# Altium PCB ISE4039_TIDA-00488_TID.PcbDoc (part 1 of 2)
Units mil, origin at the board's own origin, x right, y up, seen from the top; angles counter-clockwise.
Board outline 3000 x 2000 mil, 4 copper layers (Layer 1 - Top Layer, Layer 2 - GND, Layer 3 - PWR, Layer 4 - Bottom Layer), stack 32.634 mil thick; 131 components, 56 nets, 369 pads, 363 vias.
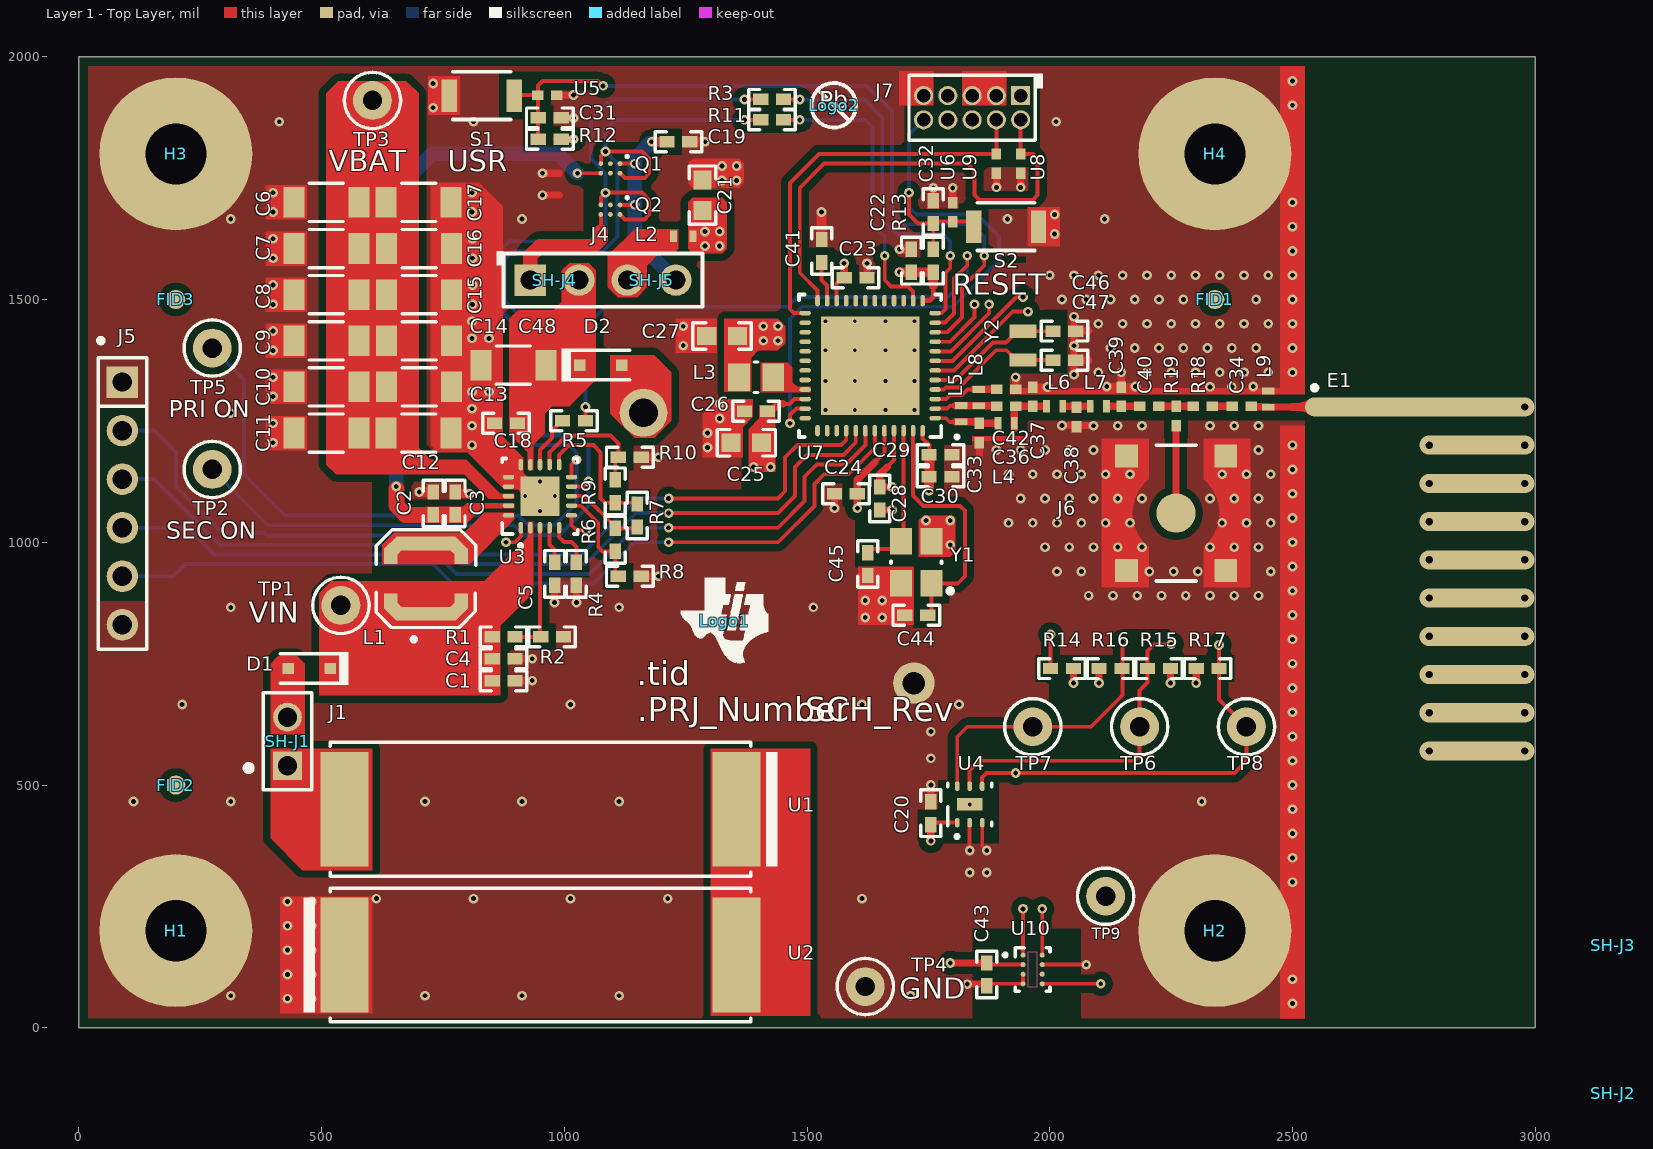
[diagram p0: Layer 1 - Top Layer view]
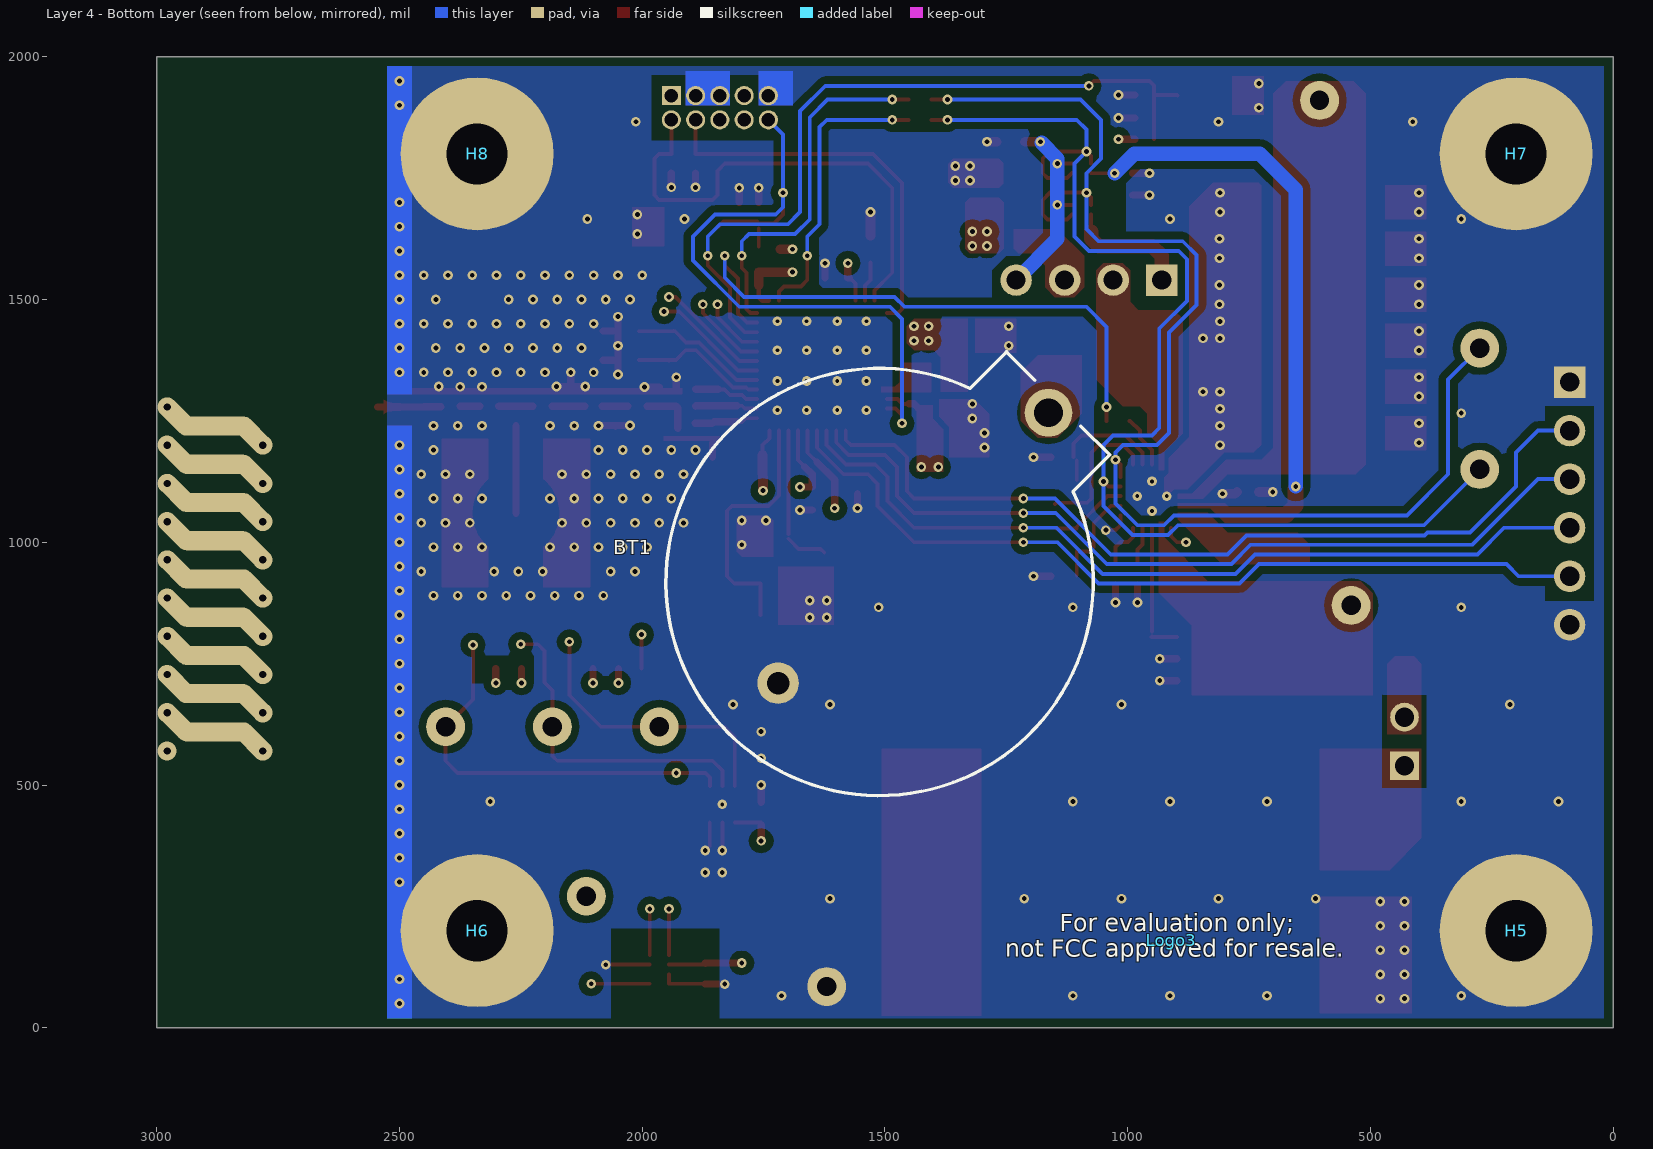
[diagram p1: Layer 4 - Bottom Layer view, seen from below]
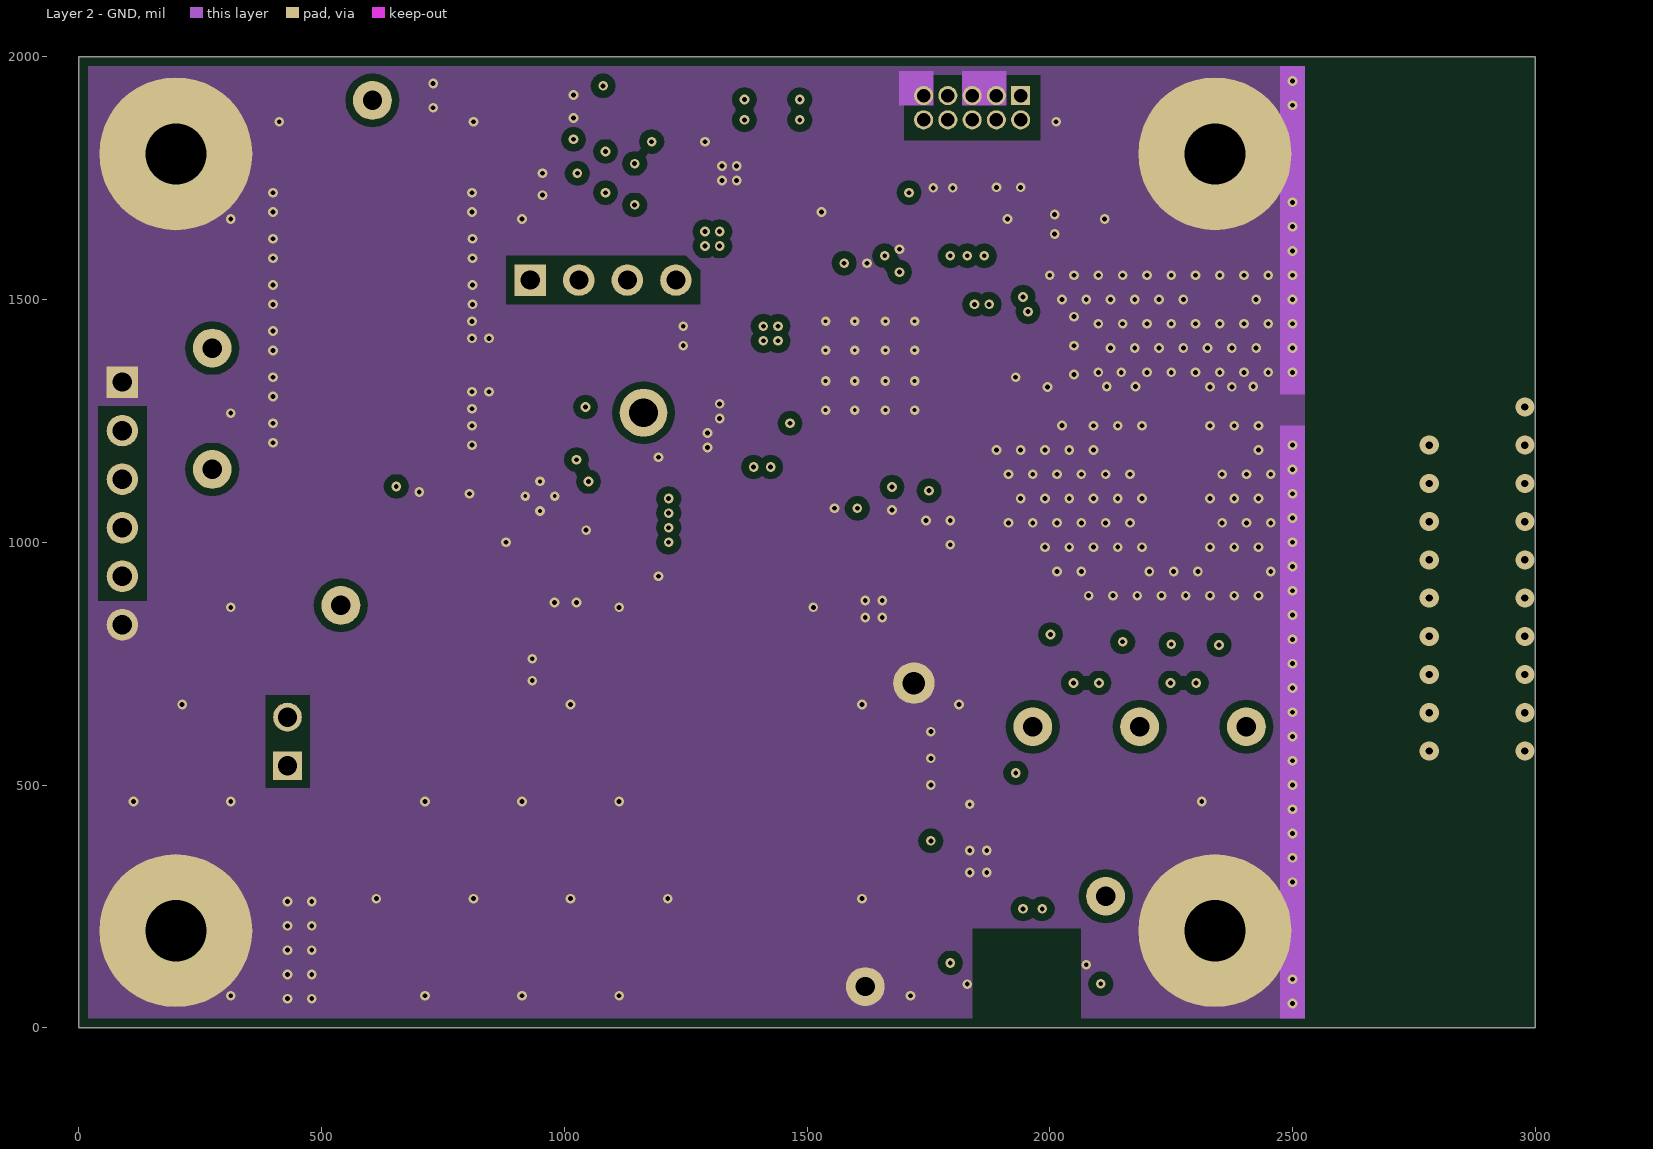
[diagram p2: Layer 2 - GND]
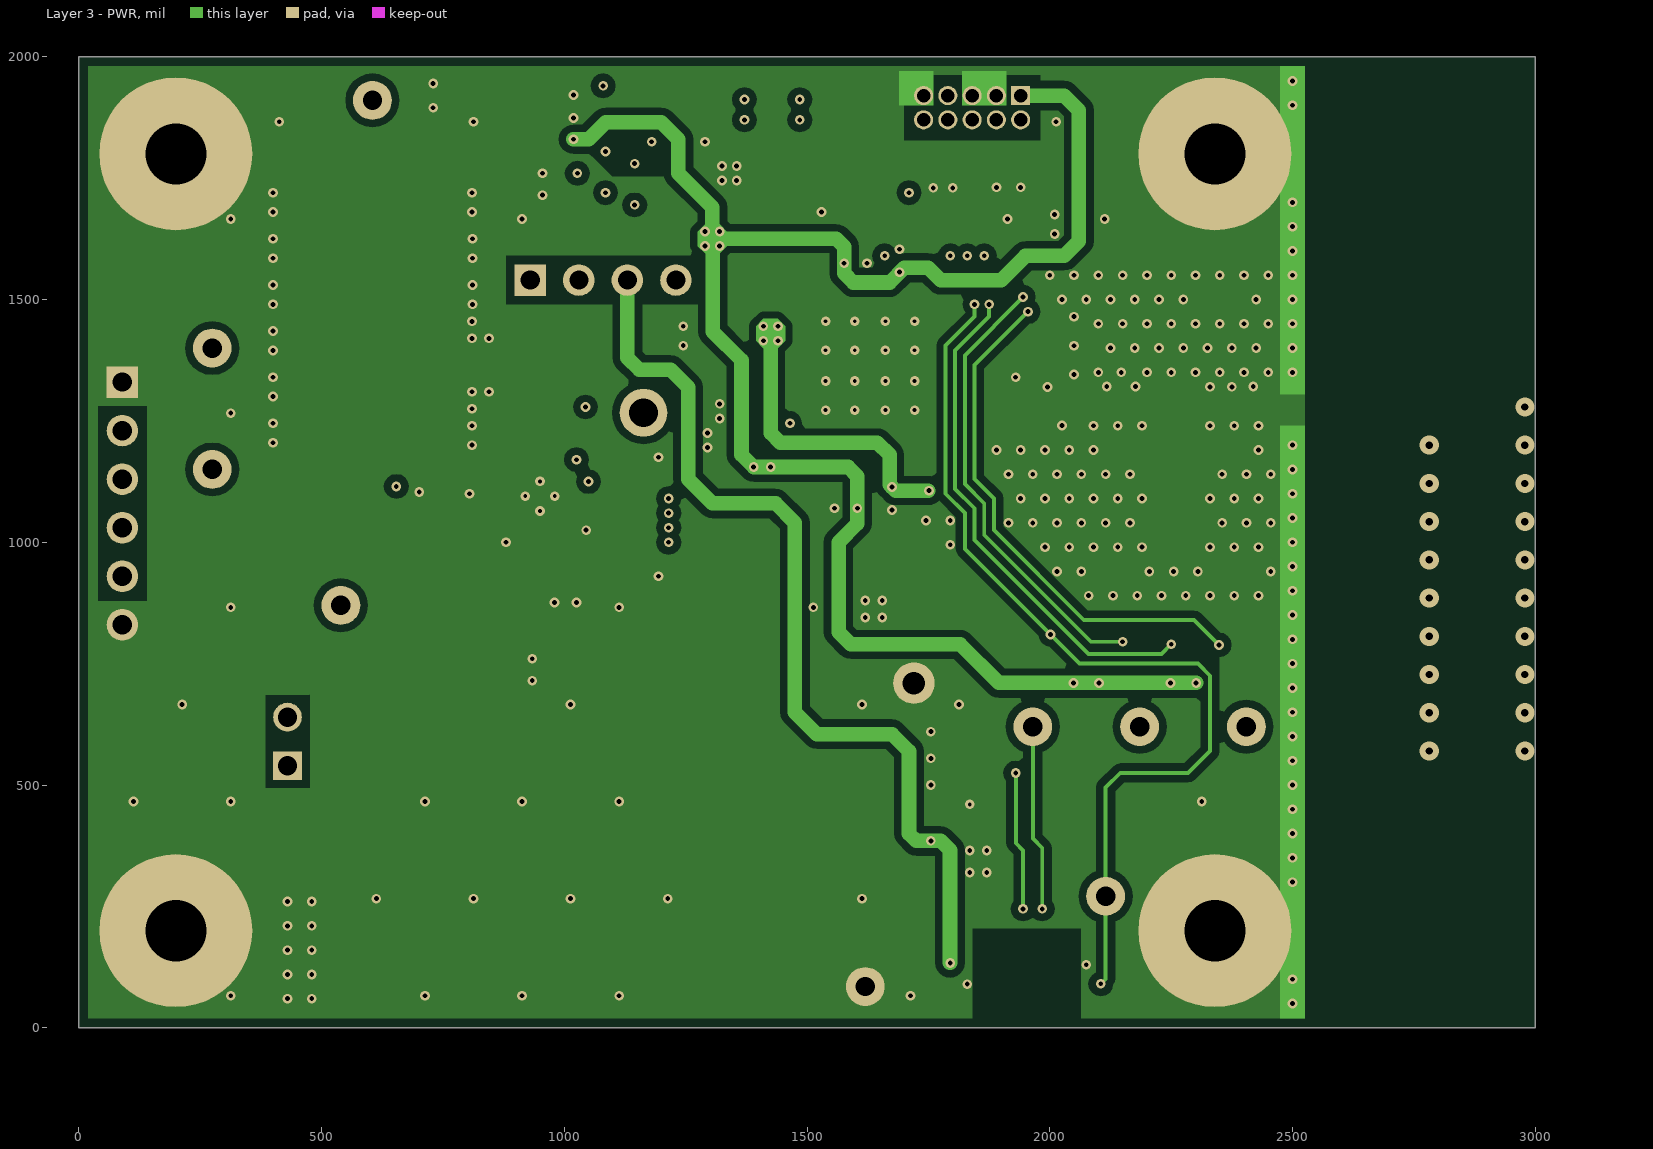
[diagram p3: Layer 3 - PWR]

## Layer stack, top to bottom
Top Solder: solder mask 0.4, Solder Resist, Dk 3.5
Layer 1 - Top Layer: signal copper 1.4
Dielectric 1: prepreg 9, 370HR, Dk 4.2
Layer 2 - GND: signal copper 1.417
Dielectric 2: core 9, 370HR, Dk 4.2
Layer 3 - PWR: signal copper 1.417
Dielectric 3: prepreg 9, 370HR, Dk 4.2
Layer 4 - Bottom Layer: signal copper 1.4
Bottom Solder: solder mask 0.4, Solder Resist, Dk 3.5

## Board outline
0,0 3000,0 3000,2000 0,2000

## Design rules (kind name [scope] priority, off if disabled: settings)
AcuteAngle [All] p1: minimum=4.50000000000000E+0001 checktracksonly=FALSE
AssemblyTestPointUsage [All] p1: valid=2
Clearance Clearance_u10 [InComponent('U10')] p1: gap=4.6
Clearance Clearance_Keepouts [((IsTrack Or IsArc) And Not InPoly) And IsFree and IsKeepOut vs ((IsTrack Or IsArc) And Not InPoly) And IsFree and IsKeepOut] p2: gap=0
Clearance Clearance_BoardEdge_MountingHoles [OnCopper and InComponentClass('Mounting Holes') vs IsKeepOut] p3: gap=40
Clearance Clearance_BoardEdge_Poly [OnCopper and InPoly vs IsKeepOut] p4: gap=25
Clearance Clearance_BoardEdge [OnCopper and Not InComponentClass('Logo') and not InComponentClass('FiducialMark') and not InRegion(1000,500,4000,800) and Not IsKeepout vs IsKeepOut] p5: gap=75
Clearance Clearance_Poly [InPolygon] p6: gap=15
Clearance [All] p7: gap=7.5
ComponentClearance ComponentClearance_MountingHoles_FiducialMarks [InComponentClass('Mounting Holes') vs InComponentClass('FiducialMark')] p1: gap=50 collisioncheckmode=3 verticalgap=10 showdistances=FALSE
ComponentClearance ComponentClearance_Shunt [InComponentClass('Header') vs InComponentClass('Shunt')] p2: gap=0 collisioncheckmode=3 verticalgap=0 showdistances=FALSE
ComponentClearance ComponentClearance_Logo [InComponentClass('Logo')] p3: gap=50 collisioncheckmode=3 verticalgap=10 showdistances=FALSE
ComponentClearance ComponentClearance_ScrewToNut [(HasFootprint('NY PMS 440 0025 PH')) vs (HasFootprint('Keystone_1902C'))] p4: gap=5 collisioncheckmode=3 verticalgap=10 showdistances=FALSE
ComponentClearance ComponentClearance_MountingHoles [InComponentClass('Mounting Holes')] p5: gap=25 collisioncheckmode=3 verticalgap=100000 showdistances=FALSE
ComponentClearance ComponentClearance_SmallPassives [HasFootprint('0201*') or HasFootprint('0402*') or HasFootprint('0508') or HasFootprint('0603*') or HasFootprint('0612') or HasFootprint('0805*') or HasFootprint('0815*') or HasFootprint('0830*') or HasFootprint('1206*') or HasFootprint('1210*') or HasFootprint('1808*') or HasFootprint('1812*') or HasFootprint('1825*') or HasFootprint('2010*') or HasFootprint('2220*') or HasFootprint('2225*') or HasFootprint('2512*') or HasFootprint('2728*') or HasFootprint('3518*') vs HasFootprint('0201*') or HasFootprint('0402*') or HasFootprint('0508') or HasFootprint('0603*') or HasFootprint('0612') or HasFootprint('0805*') or HasFootprint('0815*') or HasFootprint('0830*') or HasFootprint('1206*') or HasFootprint('1210*') or HasFootprint('1808*') or HasFootprint('1812*') or HasFootprint('1825*') or HasFootprint('2010*') or HasFootprint('2220*') or HasFootprint('2225*') or HasFootprint('2512*') or HasFootprint('2728*') or HasFootprint('3518*')] p6: gap=10 collisioncheckmode=3 verticalgap=10 showdistances=FALSE
ComponentClearance ComponentClearance_THtoSMT [IsThruComponent vs IsSMTComponent] p7: gap=18 collisioncheckmode=3 verticalgap=30 showdistances=FALSE
ComponentClearance ComponentClearance_THtoTH [IsThruComponent vs IsThruComponent] p8: gap=25 collisioncheckmode=3 verticalgap=30 showdistances=FALSE
ComponentClearance [All] p9: gap=5 collisioncheckmode=3 verticalgap=10 showdistances=FALSE
DiffPairsRouting [All] p1: maxlimit=100 minlimit=10 mostfreqgap=10 toplayer_minwidth=15 toplayer_maxwidth=15 toplayer_prefwidth=15 midlayer1_minwidth=15 midlayer1_maxwidth=15 midlayer1_prefwidth=15 midlayer2_minwidth=15 midlayer2_maxwidth=15 midlayer2_prefwidth=15 bottomlayer_minwidth=15 bottomlayer_maxwidth=15 bottomlayer_prefwidth=15 maxuncoupledlength=1000
FabricationTestPointUsage TestPointUsage [All] p1: valid=2 allowmultiple=FALSE
FabricationTestpoint Testpoint [All] p1: side=3 testpointundercomponent=TRUE minsize=40 maxsize=100 preferedsize=60 minholesize=0 maxholesize=40 preferedholesize=32 testpointgrid=1 allowsidetop=TRUE allowsidebottom=TRUE usegrid=TRUE gridtolerance=0.01
FanoutControl Fanout_LCC [IsLCC] p1: bgadir=Out bgaviamode=Centered fanoutstyle=Auto fanoutdirection=Alternating viagrid=1 // Fanout_LCC (Default Rule)
FanoutControl Fanout_BGA [IsBGA] p2: bgadir=Out bgaviamode=Centered fanoutstyle=Auto fanoutdirection=Alternating viagrid=1 // Fanout_BGA (Default Rule)
FanoutControl Fanout_Default [All] p4: bgadir=Out bgaviamode=Centered fanoutstyle=Auto fanoutdirection=Alternating viagrid=1 // Fanout_Default (Default Rule)
FanoutControl Fanout_Small [(CompPinCount < 5)] p5: bgadir=Out bgaviamode=Centered fanoutstyle=Auto fanoutdirection=OutThenIn viagrid=1 // Fanout_Small (Default Rule)
HoleSize [All] p1: absolutevalues=TRUE maxlimit=251 minlimit=7.8 maxpercent=80.000 minpercent=20.000
MinimumAnnularRing MinimumAnnularRing_ThermalPadVias [IsVia and InAnyComponent] p1: minimumring=5.91
MinimumAnnularRing [All] p2: minimumring=5
MinimumSolderMaskSliver MinimumSolderMaskSliver_Logo [InComponentClass('Logo') vs InComponentClass('Logo')] p1: minsoldermaskwidth=0.7
MinimumSolderMaskSliver [All] p2: minsoldermaskwidth=3.94
PlaneConnect [All] p1: planeconnectstyle=Relief reliefexpansion=10 reliefentries=4 reliefconductorwidth=10 reliefairgap=10
PolygonConnect [All] p1: connectstyle=Direct reliefconductorwidth=10 reliefentries=4 polygonreliefangle="90 Angle" airgapwidth=10
RoutingVias ThermalPadVias [IsVia and InAnyComponent] p1: holewidth=7.87 width=19.68 viastyle="Through Hole" minholewidth=7.87 minwidth=19.68 maxholewidth=15 maxwidth=40
RoutingVias [All] p2: holewidth=16 width=34 viastyle="Through Hole" minholewidth=7.87 minwidth=19 maxholewidth=40 maxwidth=65
SilkToBoardRegionClearance [Not ((IsComment or IsDesignator) And (Hide <> 'False')) and not InRegion(1000,500,4000,800)] p1:
SilkToSilkClearance SilkToSilkClearance_Pb-FreeLogo [(HasFootprint('Pb-Free_Overlay_Medium') OR HasFootprint('Pb-Free_Overlay_Small')) vs (HasFootprint('Pb-Free_Overlay_Medium') OR HasFootprint('Pb-Free_Overlay_Small'))] p1: silktosilkclearance=0
SilkToSilkClearance [All] p2: silktosilkclearance=4
SilkToSolderMaskClearance "Silk to Solder Mask Opening" [All] p1: minsilkscreentomaskgap=3 clearancetoexposedcopper=FALSE
SolderMaskExpansion [All] p1: expansion=1.97
UnpouredPolygon [All] p1: allowunpoured=FALSE
Width [All] p1: maxlimit=100 minlimit=6 preferedwidth=10 checkconnectedcopper=TRUE
14 further rules are at their usual default settings.

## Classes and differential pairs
component class AssemblyNote: ZZ2 ZZ3 ZZ4
component class FiducialMark: FID1 FID2 FID3
component class ISE4039_TIDA-00488_TID_Hardware: FID1 FID2 FID3 H1 H2 H3 H4 H5 H6 H7 H8 Logo1 Logo2 Logo3 SH-J1 SH-J2 SH-J3 SH-J4 SH-J5 ZZ2 ZZ3 ZZ4
component class Logo: Logo1
component class "Mounting Holes": H1 H2 H3 H4
component class Header: J1 J4 J5 J7
component class "ISE4039_TIDA-00488_Wireless MCU & Sensors": C20 C21 C22 C23 C24 C25 C26 C27 C28 C29 C30 C31 C32 C33 C34 C36 C37 C38 C39 C40 C41 C42 C43 C44 C45 C46 C47 E1 J5 J6 J7 L2 L3 L4 L5 L6 L7 L8 L9 R3 R11 R12 R13 R14 R15 R16 R17 R18 R19 S1 S2 TP6 TP7 TP8 TP9 U4 U5 U6 U7 U8 U9 U10 Y1 Y2
component class "ISE4039_TIDA-00488_Energy Harvesting": BT1 C1 C2 C3 C4 C5 C6 C7 C8 C9 C10 C11 C12 C13 C14 C15 C16 C17 C18 C19 C48 D1 D2 J1 J4 L1 Q1 Q2 R1 R2 R4 R5 R6 R7 R8 R9 R10 TP1 TP2 TP3 TP4 TP5 U1 U2 U3
component class Shunt: SH-J1 SH-J2 SH-J3 SH-J4 SH-J5

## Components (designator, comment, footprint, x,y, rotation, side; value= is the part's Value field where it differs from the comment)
BT1 "BS-7" BAT_BS-7 1441.61,988.39 r315 bottom locked
C1 "C1005X5R1A475K050BC" 0402 875,715 r0 top
C2 "C1005X5R1A475K050BC" 0402 730,1080 r90 top
C3 "GRM155R70J104KA01D" 0402 775,1080 r90 top
C4 "GRM155R70J104KA01D" 0402 875,760 r0 top
C5 "C0402C103J5RACTU" 0402 980,935 r270 top
C6 "C3216X5R1A107M160AC" 1206_190 510,1700 r180 top
C7 "C3216X5R1A107M160AC" 1206_190 510,1605 r180 top
C8 "C3216X5R1A107M160AC" 1206_190 510,1510 r180 top
C9 "C3216X5R1A107M160AC" 1206_190 510,1415 r180 top
C10 "C3216X5R1A107M160AC" 1206_190 510,1320 r180 top
C11 "C3216X5R1A107M160AC" 1206_190 510,1225 r180 top
C12 "C3216X5R1A107M160AC" 1206_190 700,1225 r0 top
C13 "C3216X5R1A107M160AC" 1206_190 701,1320 r0 top
C14 "C3216X5R1A107M160AC" 1206_190 701.12,1415 r0 top
C15 "C3216X5R1A107M160AC" 1206_190 701,1510 r0 top
C16 "C3216X5R1A107M160AC" 1206_190 701,1605 r0 top
C17 "C3216X5R1A107M160AC" 1206_190 700,1700 r0 top
C18 "C1005X5R1A475K050BC" 0402 880,1245 r180 top
C19 "GRM155R61A105KE15D" 0402 1235,1825 r0 top
C20 "GRM155R71C104KA88D" 0402 1755,442 r270 top
C21 "Used in BOM report" 0603 1285,1715 r90 top
C22 "GRM155R71C104KA88D" 0402 1715,1580 r90 top
C23 "GRM155R71C104KA88D" 0402 1600,1545 r0 top
C24 "GRM155R71C104KA88D" 0402 1580,1100 r180 top
C25 "C1608X5R0J226M080AC" 0603 1375,1205 r180 top
C26 "GRM155R71C104KA88D" 0402 1395,1270 r180 top
C27 "C1608X5R0J226M080AC" 0603 1325,1425 r180 top
C28 "GRM155R71C104KA88D" 0402 1650,1090 r270 top
C29 "GRM155R71C104KA88D" 0402 1775,1180 r0 top
C30 "GRM155R71C104KA88D" 0402 1775,1135 r0 top
C31 "C1005X7R1H222K" 0402 970.32,1874 r180 top
C32 "C1005X7R1H222K" 0402 1760,1680 r270 top
C33 "GRM1555C1H3R6CA01D" 0402L 1855,1225 r90 top
C34 "GJM1555C1HR60BB01D" 0402L 2395,1280 r180 top
C36 "GRM1555C1H3R6CA01D" 0402L 1910,1280 r180 top
C37 "GRM1555C1H2R7CA01D" 0402L 1965,1300 r90 top
C38 "GRM1555C1H6R2CA01D" 0402L 2055,1258 r270 top
C39 "GRM1555C1H3R3CA01D" 0402L 2147,1300 r90 top
C40 "GRM1555C1H101JA01D" 0402L 2205,1280 r180 top
C41 "C1005X5R1C105K050BC" 0402 1530,1600 r270 top
C42 "GRM1555C1H101JA01D" 0402L 1910,1315 r0 top
C43 "GRM155R71C104KA88D" 0402 1870,110 r90 top
C44 "GRM1555C1E120JA01D" 0402 1725,850 r180 top
C45 "GRM1555C1E120JA01D" 0402 1625,955 r270 top
C46 "GRM1555C1E120JA01D" 0402 2030,1435 r180 top
C47 "GRM1555C1E120JA01D" 0402 2030,1375 r180 top
C48 "C3216X5R1A107M160AC" 1206_190 895,1365 r180 top
D1 "1SS315TPH3F" sod-323 475,740 r180 top
D2 "1SS315TPH3F" sod-323 1075,1365 r0 top
E1 "ANTENNA_HELICAL" ANTENNA_HELICAL 2545.35,1278.74 r270 top net-tie
FID1 "Fiducial" Fiducial10-20 2340,1500 r0 top
FID2 "Fiducial" Fiducial10-20 200,500 r0 top
FID3 "Fiducial" Fiducial10-20 200,1500 r0 top
H1 "NY PMS 440 0025 PH" "NY PMS 440 0025 PH" 200,200 r0 top locked
H2 "NY PMS 440 0025 PH" "NY PMS 440 0025 PH" 2340,200 r180 top
H3 "NY PMS 440 0025 PH" "NY PMS 440 0025 PH" 200,1800 r0 top locked
H4 "NY PMS 440 0025 PH" "NY PMS 440 0025 PH" 2340,1800 r0 top locked
H5 "1902C" Keystone_1902C 200,200 r180 bottom locked
H6 "1902C" Keystone_1902C 2340,200 r0 bottom locked
H7 "1902C" Keystone_1902C 200,1800 r180 bottom locked
H8 "1902C" Keystone_1902C 2340,1800 r180 bottom locked
J1 "PEC02SAAN" CONN_PEC02SAAN 430,590 r90 top
J4 "PEC04SAAN" SULLINS_PEC04SAAN 1080,1540 r0 top
J5 "TSW-106-07-G-S" TSW-106-07-G-S 90,1080 r270 top
J6 "CONSMA001-SMD-G" Linx_CONSMA001-SMD-G 2260,1060 r0 top
J7 "GRPB052VWVN-RC" CONN_GRPB052VWVN-RC 1840,1895 r180 top
L1 "LPS4018-223MLB" LPS4018 715,925 r90 top
L2 "BLM18HE152SN1D" 0402S 1245,1630 r180 top
L3 "MLZ2012N6R8LT000" 0805_145 1395,1340 r180 top
L4 "LQW15AN7N5G00D" LQW15A_00_10 1910,1245 r0 top
L5 "LQW15AN18NJ00D" LQW15A_00_10 1818,1265 r90 top
L6 "LQW15AN6N8G00D" LQW15A_00_10 2010,1280 r0 top
L7 "LQW15AN6N8G00D" LQW15A_00_10 2100,1280 r0 top
L8 "LQW15AN7N5G00D" LQW15A_00_10 1854,1298 r270 top
L9 "LQW15AN11NG00D" LQW15A_00_10 2450,1295 r270 top
Logo1 "Texas Instruments" TI_Symbol_Overlay_Small 1329.8,838.55 r0 top
Logo2 "Pb-Free Symbol" Pb-Free_Overlay_Small 1555,1900 r0 top
Logo3 "FCC disclaimer" FCC_disclaimer_stacked 910,180 r180 bottom
Q1 "CSD75208W1015" YZC0006ABBB 1095,1770 r270 top
Q2 "CSD75208W1015" YZC0006ABBB 1095,1685 r270 top
R1 "CRCW04024M12FKED" 0402 875,805 r180 top
R2 "CRCW04025M76FKED" 0402 975,805 r180 top
R3 "CRCW04020000Z0ED" 0402 1428,1912 r0 top
R4 "CRCW04020000Z0ED" 0402 1025,935 r270 top
R5 "CRCW04020000Z0ED" 0402 1020,1250 r180 top
R6 "CRCW04026M19FKED" 0402 1105,1005 r90 top
R7 "CRCW04023M09FKED" 0402 1150,1055 r270 top
R8 "CRCW04026M65FKED" 0402 1135,930 r180 top
R9 "CRCW04023M57FKED" 0402 1105,1105 r270 top
R10 "CRCW04026M19FKED" 0402 1135,1175 r180 top
R11 "CRCW04020000Z0ED" 0402 1428,1870 r0 top
R12 "CRCW040247K5FKED" 0402 970.32,1830 r0 top
R13 "CRCW040247K5FKED" 0402 1760,1580 r270 top
R14 "CRCW040210K0FKED" 0402 2025,740 r0 top
R15 "CRCW040210K0FKED" 0402 2225,740 r0 top
R16 "CRCW04024K75FKED" 0402 2125,740 r180 top
R17 "CRCW04024K75FKED" 0402 2325,740 r180 top
R18 "CRCW04020000Z0ED" 0402L 2315,1280 r0 top
R19 "CRCW04020000Z0ED" 0402L 2260,1260 r270 top
S1 "B3U-1000P" SW_B3U-1000P 830,1920 r0 top
S2 "B3U-1000P" SW_B3U-1000P 1910,1650 r180 top
SH-J1 "2SN-BK-G" 2SN-BK-G 430,590 r90 top
SH-J2 "2SN-BK-G" 2SN-BK-G 3160,-135 r90 top
SH-J3 "2SN-BK-G" 2SN-BK-G 3160,170 r90 top
SH-J4 "2SN-BK-G" 2SN-BK-G 980,1540 r180 top
SH-J5 "2SN-BK-G" 2SN-BK-G 1180,1540 r180 top
TP1 "5000" Keystone5000 540,870 r0 top
TP2 "5000" Keystone5000 275,1150 r90 top
TP3 "5000" Keystone5000 605,1910 r0 top
TP4 "5001" Keystone5001 1620,85 r0 top
TP5 "5000" Keystone5000 275,1400 r90 top
TP6 "5000" Keystone5000 2185,620 r0 top
TP7 "5000" Keystone5000 1965,620 r0 top
TP8 "5000" Keystone5000 2405,620 r0 top
TP9 "5000" Keystone5000 2115,271 r0 top
U1 "KXOB22-12X1L" IXYS_KXOB22-12X1L 951,450 r0 top
U2 "KXOB22-12X1L" IXYS_KXOB22-12X1L 951,150 r180 top
U3 "BQ25505RGRR" RGR0020A 950,1094.96 r90 top
U4 "OPT3001DNP" DNP0006A 1835,460 r90 top
U5 "TPD1E10B06DPYR" DPY0002A 965.32,1921 r0 top
U6 "TPD1E10B06DPYR" DPY0002A 1800,1680 r90 top
U7 "CC1310F128RGZR" RGZ0048A 1629.88,1363.76 r180 top
U8 "TPD1E10B06DPYR" DPY0002A 1940,1780 r270 top
U9 "TPD1E10B06DPYR" DPY0002A 1890,1780 r270 top
U10 "HDC1000YPAR" YPA0008AGAE 1964.69,120.16 r0 top
Y1 "TSX-3225 24.0000MF20G-AC3" EPSON_TSX-3225 1725,958.76 r180 top
Y2 "FC-12M 32.7680KA-A3" Epson_FC-12M 1945,1405 r90 top
ZZ2 "These assemblies are ESD sensitive, ESD precautions shall be observed." AssemblyNote 100,2400 r0 top
ZZ3 "These assemblies must be clean and free from flux and all contaminants. Use of no clean flux is not acceptable." AssemblyNote 100,2300 r0 top
ZZ4 "These assemblies must comply with workmanship standards IPC-A-610 Class 2, unless otherwise specified." AssemblyNote 100,2200 r0 top

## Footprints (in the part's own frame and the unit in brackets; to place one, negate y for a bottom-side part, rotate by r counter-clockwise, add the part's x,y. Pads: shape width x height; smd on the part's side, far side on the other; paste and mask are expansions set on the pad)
2SN-BK-G [mil] "Samtec STEP model"
  round 1 on Mech3: 0(0,0)
  body extent -78,-39 79,39, height 188
0402 [mm] "0402 from SM-752 data"
  rect 0.8x0.6 smd: 1(-0.6,0) 2(0.6,0)
  silkscreen extent -1.22,-0.52 1.22,0.52, body extent -0.55,-0.3 0.55,0.3, height 0.6
0402L [mm] "0402 from SM-752 data"
  rect 0.6x0.5 smd: 1(-0.5,0) 2(0.5,0)
  body extent -0.55,-0.3 0.55,0.3, height 0.6
0402S [mil] "Based on C0402S footprint from PADS legacy"
  rect 15x24 smd: 1(-20,0) 2(20,0)
  body extent -22,-12 22,12, height 24
0603 [mm] "0603 from SM-752 data"
  rect 1x0.95 smd: 1(-0.8,0) 2(0.8,0)
  silkscreen extent -1.52,-0.69 1.52,0.69, body extent -0.87,-0.47 0.87,0.47, height 0.85
0805_145 [mm] "0805 / 1.45mm height"
  rect 1.15x1.45 smd: 1(-0.9,0) 2(0.9,0)
  silkscreen extent -0.1,-0.8 0.1,0.8, body extent -1.1,-0.72 1.1,0.72, height 1.45
1206_190 [mm] "1206_190"
  rect 1.1x1.6 smd: 1(-1.7,0) 2(1.7,0)
  silkscreen extent -0.9,-1 0.9,1, body extent -1.75,-0.95 1.75,0.95, height 1.9
ANTENNA_HELICAL [mm] "SMD, 1-Lead"
  round 1 smd paste-1 mask-1: 1(0,0)
  oval 1x12 smd paste-12 mask-12: ""(0,5.5)
  oval 1x2.414 smd far side rot 45 paste-1.5 mask-1.5: ""(0.5,10.5) ""(1.5,6.5) ""(2.5,10.5) ""(3.5,6.5) ""(4.5,10.5) ""(5.5,6.5) ""(6.5,10.5) ""(7.5,6.5) ""(8.5,10.5) ""(9.5,6.5) ""(10.5,10.5) ""(11.5,6.5) ""(12.5,10.5) ""(13.5,6.5) ""(14.5,10.5) ""(15.5,6.5) ""(16.5,10.5) ""(17.5,6.5)
  oval 1x4 smd far side paste-4 mask-4: ""(1,8.5) ""(3,8.5) ""(5,8.5) ""(7,8.5) ""(9,8.5) ""(11,8.5) ""(13,8.5) ""(15,8.5) ""(17,8.5)
  oval 1x6 smd paste-6 mask-6: ""(2,8.5) ""(4,8.5) ""(6,8.5) ""(8,8.5) ""(10,8.5) ""(12,8.5) ""(14,8.5) ""(16,8.5) ""(18,8.5)
  silkscreen extent -1.12,-0.12 -0.88,0.13
AssemblyNote [mil] "Assembly Note"
BAT_BS-7 [mm] "Memory Protection Devices CR2032 battery holder"
  round 2.5 hole 1.5: 1(-10,0)
  round 2.17 hole 1.181: 2(10,0)
  silkscreen extent -10.7,-11.16 13.68,11.18, body extent -10.69,-11.16 13.7,11.16, height 9.02
CONN_GRPB052VWVN-RC [mm] "SULLINS"
  rect 1x1 hole 0.7 mask+0.08: 1(-2.54,-0.635)
  round 1 hole 0.7 mask+0.08: 2(-2.54,0.635) 3(-1.27,-0.635) 4(-1.27,0.635) 5(0,-0.635) 6(0,0.635) 7(1.27,-0.635) 8(1.27,0.635) 9(2.54,-0.635) 10(2.54,0.635)
  silkscreen extent -3.7,-1.8 3.3,1.7, body extent -3.17,-1.7 3.17,1.7, height 4
CONN_PEC02SAAN [mm] "SULLINS"
  rect 1.5x1.5 hole 1.016: 1(-1.27,0)
  round 1.5 hole 1.016: 2(1.27,0)
  silkscreen extent -2.54,-1.27 2.54,2.16, body extent -2.54,-1.27 2.54,1.27, height 8.38
DNP0006A [mm] "DFN-6 2x2mm"
  oval 0.5x0.25 smd: 1(-0.95,0.65) 2(-0.95,0) 3(-0.95,-0.655) 4(0.95,-0.65) 5(0.95,0) 6(0.95,0.65)
  rect 0.65x1.35 smd paste-0.5: 7(0,0)
  silkscreen extent -1.12,-1.15 1.12,1.15, body extent -1,-1 1,1, height 0.64
DPY0002A [mm] "R-PX2SON-N2"
  rect 0.6x0.5 smd: 1(-0.5,0) 2(0.5,0)
  body extent -0.55,-0.35 0.55,0.35, height 0.4
Epson_FC-12M [mm] "Epson"
  rect 0.7x1.4 smd: 1(-0.75,0) 2(0.75,0)
  body extent -1.05,-0.63 1.05,0.63, height 0.6
EPSON_TSX-3225 [mm] "SMD, 4-Leads, Body 2.65x3.35mm, Height 0.6mm"
  rect 1.15x1.4 smd: 1(-0.8,1.1) 2(-0.8,-1.1) 3(0.8,-1.1) 4(0.8,1.1)
  silkscreen extent -1.9,-0.05 1.33,1.62, body extent -1.33,-1.68 1.33,1.68, height 0.61
FCC_disclaimer_stacked [mil]
Fiducial10-20 [mm]
  round 1 smd mask+0.5: 1(0,0)
IXYS_KXOB22-12X1L [mm] "SMD, Body 22x7mm"
  rect 2.5x6 smd: 1(-10.25,0) 2(10.25,0)
  silkscreen extent -11,-3.5 12.4,3.5, body extent -11,-3.5 11,3.5, height 1.81
Keystone5000 [mil] "For Keystone 500x miniature loop terminals"
  round 80 hole 40: 1(0,0)
  silkscreen extent -58,-58 58,58, body extent -49,-49 49,49, height 182
Keystone5001 [mil] "For Keystone 500x miniature loop terminals"
  round 80 hole 40: 1(0,0)
  silkscreen extent -58,-58 58,58, body extent -49,-49 49,49, height 182
Keystone_1902C [mil] "Hex Standoff, 4-40 threaded, nylon"
  body extent -145,-126 146,126, height 501
Linx_CONSMA001-SMD-G [mm] "SMD, 5-Leads, Body 7x7mm, Height 10.5mm"
  round 2.05 smd: 1(0,0)
  rect 1.2x1.2 smd: 2(-2.6,-3) 3(2.6,-3) 4(2.6,3) 5(-2.6,3)
  Layer 1 - Top Layer region: 3.88,-3.88 1.44,-3.88 1.44,-1.761 1.448,-1.761 2.062,-0.974 2.28,0 2.062,0.974 1.448,1.761 1.448,1.761 1.44,1.761 1.44,3.88 3.88,3.88
  Layer 1 - Top Layer region: -3.88,-3.88 -1.44,-3.88 -1.44,-1.761 -1.448,-1.761 -2.062,-0.974 -2.28,0 -2.062,0.974 -1.448,1.761 -1.448,1.761 -1.44,1.761 -1.44,3.88 -3.88,3.88
  silkscreen extent -1.04,-3.55 1.04,3.55, body extent -3.55,-3.55 3.55,3.55, height 10.5
LPS4018 [mil]
  rect 28x123 smd: 1(-72.5,0) 2(72.5,0)
  rect 35.5x28 smd rot 45: 1(-64,64) 2(64.5,-63.5)
  rect 35.5x28 smd rot 135: 1(-64,-64) 2(64,64)
  rect 31.5x28 smd: 1(-46,72.5) 1(-46,-72.5) 2(46,72.5) 2(46,-72.5)
  silkscreen extent -129,-102 100,102, body extent -81,-81 81,81, height 71
LQW15A_00_10 [mm] "Murata"
  rect 0.35x0.65 smd: 1(-0.425,0) 2(0.425,0)
  body extent -0.55,-0.35 0.55,0.35, height 0.6
"NY PMS 440 0025 PH" [mm] "4-40 nylon screw and mounting hole"
  round 8 hole 3.2: 1(0,0)
  body extent -3.3,-3.3 3.3,3.3, height 2.69
Pb-Free_Overlay_Small [mil]
  silkscreen extent -46,-46 46,46
RGR0020A [mm] "QFN, 20-Leads, Body 3.5x3.5mm, Pitch 0.5mm, Thermal Pad 2.05x2.05mm, TI Recommended"
  oval 0.6x0.24 smd: 1(-1.65,1) 2(-1.65,0.5) 3(-1.65,0) 4(-1.65,-0.5) 5(-1.65,-1) 11(1.65,-1) 12(1.65,-0.5) 13(1.65,0) 14(1.65,0.5) 15(1.65,1)
  oval 0.24x0.6 smd: 6(-1,-1.65) 7(-0.5,-1.65) 8(0,-1.65) 9(0.5,-1.65) 10(1,-1.65) 16(1,1.65) 17(0.5,1.65) 18(0,1.65) 19(-0.5,1.65) 20(-1,1.65)
  rect 2.05x2.05 smd paste-1.025: 21(0,0)
  silkscreen extent -1.97,-1.97 1.97,1.97, body extent -1.83,-1.83 1.83,1.83, height 1.01
RGZ0048A [mm] "QFN, 48-Leads, Body 7x7mm, Pitch 0.5mm, Thermal Pad 5.15X5.15mm, TI recommended"
  oval 0.6x0.24 smd: 1(-3.4,2.75) 2(-3.4,2.25) 3(-3.4,1.75) 4(-3.4,1.25) 5(-3.4,0.75) 6(-3.4,0.25) 7(-3.4,-0.25) 8(-3.4,-0.75) 9(-3.4,-1.25) 10(-3.4,-1.75) 11(-3.4,-2.25) 12(-3.4,-2.75) 25(3.4,-2.75) 26(3.4,-2.25) 27(3.4,-1.75) 28(3.4,-1.25) 29(3.4,-0.75) 30(3.4,-0.25) 31(3.4,0.25) 32(3.4,0.75) 33(3.4,1.25) 34(3.4,1.75) 35(3.4,2.25) 36(3.4,2.75)
  oval 0.24x0.6 smd: 13(-2.75,-3.4) 14(-2.25,-3.4) 15(-1.75,-3.4) 16(-1.25,-3.4) 17(-0.75,-3.4) 18(-0.25,-3.4) 19(0.25,-3.4) 20(0.75,-3.4) 21(1.25,-3.4) 22(1.75,-3.4) 23(2.25,-3.4) 24(2.75,-3.4) 37(2.75,3.4) 38(2.25,3.4) 39(1.75,3.4) 40(1.25,3.4) 41(0.75,3.4) 42(0.25,3.4) 43(-0.25,3.4) 44(-0.75,3.4) 45(-1.25,3.4) 46(-1.75,3.4) 47(-2.25,3.4) 48(-2.75,3.4)
  rect 5.15x5.15 smd paste-2.6: 49(0,0)
  silkscreen extent -3.72,-3.72 3.72,3.72, body extent -3.58,-3.57 3.57,3.58, height 1.01
sod-323 [mm] "NXP recommended land pattern"
  rect 0.6x0.6 smd paste-0.05: 1(-1.1,0) 2(1.1,0)
  silkscreen extent -2.06,-0.86 1.53,0.86, body extent -1.3,-0.67 1.3,0.68, height 1.1
SULLINS_PEC04SAAN [mm] "SULLINS"
  rect 1.65x1.65 hole 1: 1(-3.81,0)
  round 1.65 hole 1: 2(-1.27,0) 3(1.27,0) 4(3.81,0)
  silkscreen extent -5.59,-1.4 5.21,1.52, body extent -5.21,-1.33 5.21,1.33, height 8.38
SW_B3U-1000P [mm] "OMRON"
  rect 0.8x1.7 smd: 1(-1.7,0) 2(1.7,0)
  silkscreen extent -1.5,-1.25 1.5,1.25, body extent -1.5,-1.25 1.5,1.25, height 1.75
TI_Symbol_Overlay_Small [mil]
  silkscreen extent -90,-88 91,88
TSW-106-07-G-S [mm] "Samtec 100mil, 1x6, 230 mil above insulator"
  rect 1.65x1.65 hole 1.016 mask+0: 1(-6.35,0)
  round 1.65 hole 1.016 mask+0: 2(-3.81,0) 3(-1.27,0) 4(1.27,0) 5(3.81,0) 6(6.35,0)
  silkscreen extent -8.64,-1.27 7.62,1.27, body extent -7.62,-1.27 7.62,1.27, height 8.38
YPA0008AGAE [mm] "BGA, 8-Leads, Body 2.04x1.59mm, Pitch 0.5mm"
  round 0.263 smd paste-0.14: A1(-0.5,0.75) A2(0.5,0.75) B1(-0.5,0.25) B2(0.5,0.25) C1(-0.5,-0.25) C2(0.5,-0.25) D1(-0.5,-0.75) D2(0.5,-0.75)
  Layer 1 - Top Layer keep-out region: -0.25,-0.899 0.25,-0.899 0.25,0.901 -0.25,0.901
  silkscreen extent -0.91,-1.14 0.91,1.14, body extent -0.81,-1.04 0.81,1.04, height 0.68
YZC0006ABBB [mm] "DSBGA"
  round 0.25 smd paste-0.125 mask+0.05: A1(-0.25,0.5) A2(0.25,0.5) B1(-0.25,0) B2(0.25,0) C1(-0.25,-0.5) C2(0.25,-0.5)
  silkscreen extent -0.68,0.82 -0.58,0.93, body extent -0.5,-0.75 0.5,0.75, height 0.62

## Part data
BT1: "Battery Holder, CR2032, Retainer clip, TH"
C1 C2 C18: "CAP, CERM, 4.7 µF, 10 V, +/- 10%, X5R, 0402"
C3 C4: "CAP, CERM, 0.1 µF, 6.3 V, +/- 10%, X7R, 0402"
C5: "CAP, CERM, 0.01 µF, 50 V, +/- 5%, X7R, 0402"
C6 C7 C8 C9 C10 C11 C12 C13 C14 C15 C16 C17 C48: "CAP, CERM, 100 µF, 10 V, +/- 20%, X5R, 1206_190"
C19: "CAP, CERM, 1 µF, 10 V, +/- 10%, X5R, 0402"
C20 C22 C23 C24 C26 C28 C29 C30 C43: "CAP, CERM, 0.1 µF, 16 V, +/- 10%, X7R, 0402"
C21: library part Capacitor, "CAP, CERM, xxxF, xxV, [TempCo], xx%, [PackageReference]"
C25 C27: "CAP, CERM, 22 µF, 6.3 V, +/- 20%, X5R, 0603"
C31 C32: "CAP, CERM, 2200 pF, 50 V, +/- 10%, X7R, 0402"
C33 C36: "CAP, CERM, 3.6 pF, 50 V, +/- 5%, C0G/NP0, 0402"
C34: library part Capacitor, "CAP, CERM, 0.6pF, 50V, NP0/C0G, +-0.1pF, 0402"
C37: "CAP, CERM, 2.7 pF, 50 V, +/- 5%, C0G/NP0, 0402"
C38: "CAP, CERM, 6.2 pF, 50 V, +/- 5%, C0G/NP0, 0402"
C39: "CAP, CERM, 3.3 pF, 50 V, +/- 5%, C0G/NP0, 0402"
C40 C42: "CAP, CERM, 100 pF, 50 V, +/- 5%, C0G/NP0, 0402"
C41: "CAP, CERM, 1 µF, 16 V, +/- 10%, X5R, 0402"
C44 C45 C46 C47: "CAP, CERM, 12 pF, 25 V, +/- 5%, C0G/NP0, 0402"
D1 D2: "Diode, Schottky, 5V, 0.03A, SOD-323"
E1: "PCB Antenna. There is nothing to buy or mount."
FID1 FID2 FID3: "Fiducial mark.  There is nothing to buy or mount."
H1 H2 H3 H4: "Machine Screw, Round, #4-40 x 1/4, Nylon, Philips panhead"
H5 H6 H7 H8: "Standoff, Hex, 0.5\"L #4-40 Nylon"
J1: "Header, 100mil, 2x1, Tin, TH"
J4: "Header, 100mil, 4x1, Tin, TH"
J5: "Header, 100mil, 6x1, Gold, TH"
J6: "Jack, SMA, PCB, Gold, SMT"
J7: "Header, 50mil, 5x2, Gold, TH"
L1: "Inductor, Shielded Drum Core, Ferrite, 22 µH, 0.83 A, 0.36 ohm, SMD"
L2: "Ferrite Bead, 1500 ohm @ 100 MHz, 0.5 A, 0603_950"
L3: "Inductor, Multilayer, Ferrite, 6.8 µH, 0.11 A, 0.25 ohm, SMD"
L4 L8: "Inductor, Wirewound, 7.5 nH, 0.57 A, 0.13 ohm, SMD"
L5: "Inductor, Wirewound, 18 nH, 0.37 A, 0.27 ohm, SMD"
L6 L7: "Inductor, Wirewound, 6.8 nH, 0.7 A, 0.09 ohm, SMD"
L9: "Inductor, Wirewound, 11 nH, 0.5 A, 0.14 ohm, SMD"
Logo1: library part TI_Logo, "Texas Instrument Corporate Signature"
Logo2: library part Pb-Free
Logo3: library part FCC_disclaimer, "FCC_disclaimer"
Q1 Q2: "MOSFET, P-CH, -20 V, -1.6 A,"
R1: "RES, 4.12 M, 1%, 0.063 W, 0402"
R2: "RES, 5.76 M, 1%, 0.063 W, 0402"
R3 R4 R5 R11 R18 R19: "RES, 0, 5%, 0.063 W, 0402"
R6 R10: "RES, 6.19 M, 1%, 0.063 W, 0402"
R7: "RES, 3.09 M, 1%, 0.063 W, 0402"
R8: "RES, 6.65 M, 1%, 0.063 W, 0402"
R9: "RES, 3.57 M, 1%, 0.063 W, 0402"
R12 R13: "RES, 47.5 k, 1%, 0.063 W, 0402"
R14 R15: "RES, 10.0 k, 1%, 0.063 W, 0402"
R16 R17: "RES, 4.75 k, 1%, 0.063 W, 0402"
S1 S2: "SWITCH TACTILE SPST-NO 0.05A 12V"
SH-J1 SH-J2 SH-J3 SH-J4 SH-J5: "Shunt, 2mm, Gold plated, Black"
TP1 TP2 TP3 TP5 TP6 TP7 TP8 TP9: "Test Point, Miniature, Red, TH"
TP4: "Test Point, Miniature, Black, TH"
U1 U2: "Monocrystalline Solar Cell, 22 X 7mm, SMD"
U3: "Ultra Low Power Boost Converter with Battery Management for Energy Harvester Applications, RGR0020A"
U4: "Ambient Light Sensor, DNP0006A"
U5 U6 U8 U9: "ESD in 0402 Package with 10 pF Capacitance and 6 V Breakdown, 1 Channel, -40 to +125 degC, 2-pin X2SON (DPY), Green (RoHS & no Sb/Br)"
U7: "Sub-1 GHz and 2.4 GHz Multi-standard RF IC Family, RGZ0048A"
U10: "HDC1000 Low power integrated humidity and temperature Sensor, YPA0008AGAE"
Y1: "Crystal, 24 MHz, 9 pF, SMD"
Y2: "Crystal, 32.768kHz, 12.5pF, SMD"
ZZ2 ZZ3 ZZ4: library part AssemblyNote

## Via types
v1: diameter 20, hole 10, Layer 1 - Top Layer to Layer 4 - Bottom Layer, tented both sides, 323 vias
v2: diameter 19.68, hole 7.87, Layer 1 - Top Layer to Layer 4 - Bottom Layer, tented both sides, 21 vias
v3: diameter 39.37, hole 14.96, Layer 1 - Top Layer to Layer 4 - Bottom Layer, 19 vias

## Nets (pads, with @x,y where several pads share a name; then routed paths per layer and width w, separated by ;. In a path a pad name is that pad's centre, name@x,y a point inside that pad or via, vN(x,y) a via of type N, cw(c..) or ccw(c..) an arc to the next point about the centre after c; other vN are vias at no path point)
DCDC_SW: L3.1 U7.33
GND: BT1.2 C1.2 C2.2 C3.2 C4.2 C5.2 C6.2 C7.2 C8.2 C9.2 C10.2 C11.2 C12.2 C13.2 C14.2 C15.2 C16.2 C17.2 C18.2 C19.2 C20.1 C21.2 C22.2 C23.2 C24.2 C25.2 C26.2 C27.2 C28.2 C29.2 C30.2 C31.1 C32.1 C33.1 C37.2 C38.2 C39.2 C41.1 C42.2 C43.1 C44.2 C45.2 C46.1 C47.1 C48.2 H1.1 H2.1 H3.1 H4.1 J5.1 J5.6 J6.2 J6.3 J6.4 J6.5 J7.3 J7.5 J7.9 L9.1 R2.1 R4.2 R8.1 R10.1 S1.1 S2.1 TP4.1 U2.2 U3.1 U3.6 U3.15 U3.16 U3.17 U3.21 U4.2 U4.3 U4.7 U5.2 U6.2 U7.49 U8.2 U9.2 U10.B2 U10.C1 U10.D1 Y1.2 Y1.4 | length 1620.2
  Layer 1 - Top Layer w8: v1(880,1000) 898.21,1000 910.63,1012.42 U3.1@910.63,1030 ; U3.6@1014.96,1055.59 1014.96,1035.04 1025,1025 v1(1045,1025) ; v1(1835,365) U4.2@1835,422.6 ; U4.3@1860.79,422.6 1860.79,374.21 v1(1870,365) ; C43.1@1870,90.32 1870.31,90.63 U10.D1@1945,90.63 U10.C1@1945,110.31 ; U10.B2@1984.37,130 v1(2075,130)
  Layer 1 - Top Layer w15: C1.2@898.62,715 v1(934,715) ; C4.2@898.62,760 v1(934,760) ; v1(955,1715) 990.31,1715 ; v1(955,1760) 990.31,1760 ; v1(980,876) C5.2@980,911.38 ; C31.1@985,1874 C31.1@993.94,1874 v1(1019,1874) ; U5.2@985,1921 v1(1019,1921) ; v1(1025,876) R4.2@1025,911.38 ; R8.1@1158.62,930 v1(1194,930) ; R10.1@1158.62,1175 v1(1194,1175) ; v1(1556.38,1070) C24.2@1556.38,1100 ; C23.2@1623.62,1545 v1(1623.62,1574.68) ; C28.2@1650,1066.38 v1(1675,1066.38) ; C20.1@1755,464 C20.1@1755,465.62 v1(1755,500) ; C32.1@1760,1699.68 C32.1@1760,1703.62 v1(1760,1730) ; U6.2@1800,1699.68 v1(1800,1730) ; v1(1830,90) 1869.69,90 C43.1@1870,90.32 ; 1855,1175 C33.1@1855,1205.32 ; v1@1890,1730 v1(1890,1730.93) U9.2@1890,1760.32 ; C42.2@1929.69,1315 v1(1929.69,1340) ; v1@1940,1730 v1(1940,1730.93) U8.2@1940,1760.32 ; C37.2@1965,1319.69 v1(1995.31,1319.69) ; v1(2025.31,1240.31) C38.2@2055,1240.31 ; v1(2049.69,1345.32) C47.1@2049.69,1375 ; v1(2049.69,1404.69) C47.1@2049.69,1375 ; v1@2049.69,1405.32 C46.1@2049.69,1435 ; v1(2049.69,1464.69) C46.1@2049.69,1435 ; C38.2@2055,1238.31 C38.2@2055,1240.31 ; 2080,1375 C47.1@2053.62,1375 C47.1@2049.69,1375 ; 2080,1435 C46.1@2053.62,1435 C46.1@2049.69,1435 ; v1@2090,1240.31 C38.2@2055,1240.31 ; v1(2117.32,1321) C39.2@2147,1321 ; C39.2@2147,1319.69 C39.2@2147,1321 ; v1(2147,1350) C39.2@2147,1321 ; v1(2176.69,1321) C39.2@2147,1321
  Layer 1 - Top Layer w20: v1(701.38,1103.62) C2.2@730,1103.62 ; C3.2@775,1103.62 778.62,1100 v1(805,1100) ; C19.2@1270,1825 v1(1290,1825) ; C41.1@1530,1631.5 v1(1530,1680) ; v1(1690.31,1603.62) C22.2@1715,1603.62
  other v1: 2500,50 430,60 480,60 313,66 713,66 913,66 1113,66 1713,66 2500,100 430,110 480,110 430,160 480,160 430,210 480,210 430,260 480,260 613,266 813,266 1013,266 1213,266 1613,266 2500,300 1835,320 1870,320 2500,350 2500,400 2500,450 113,466 313,466 713,466 913,466 1113,466 2313,466 2500,500 2500,550 1755,555 2500,600 1755,610 2500,650 213,666 1013,666 1613,666 1813,666 2500,700 2500,750 2500,800 1620,845 1655,845 2500,850 313,866 1113,866 1513,866 1620,880 1655,880 2080,890 2130,890 2180,890 2230,890 2280,890 2330,890 2380,890 2430,890 2500,900 2015,940 2065,940 2205,940 2255,940 2305,940 2455,940 2500,950 1990,990 2040,990 2090,990 2140,990 2190,990 2330,990 2380,990 2430,990 1795,995 2500,1000 1915,1040 1965,1040 2015,1040 2065,1040 2115,1040 2165,1040 2355,1040 2405,1040 2455,1040 1745,1045 1795,1045 2500,1050 1940,1090 1990,1090 2040,1090 2090,1090 2140,1090 2190,1090 2330,1090 2380,1090 2430,1090 2500,1100 1915,1140 1965,1140 2015,1140 2065,1140 2115,1140 2165,1140 2355,1140 2405,1140 2455,1140 2500,1150 1890,1190 1940,1190 1990,1190 2040,1190 2090,1190 2430,1190 1295,1195 810,1200 2500,1200 400,1205 1295,1225 810,1240 2090,1240 2140,1240 2190,1240 2330,1240 2380,1240 2430,1240 400,1245 1320,1255 313,1266 810,1275 1320,1285 400,1300 810,1310 845,1310 2330,1320 2375,1320 2419,1321 400,1340 2100,1350 2200,1350 2250,1350 2300,1350 2350,1350 2400,1350 2450,1350 2500,1350 400,1395 2125,1400 2175,1400 2225,1400 2275,1400 2325,1400 2375,1400 2425,1400 2500,1400 1245,1405 810,1420 845,1420 400,1435 1245,1445 2100,1450 2150,1450 2200,1450 2250,1450 2300,1450 2350,1450 2400,1450 2450,1450 2500,1450 810,1455 400,1490 811,1490 2025,1500 2075,1500 2125,1500 2175,1500 2225,1500 2275,1500 2425,1500 2500,1500 400,1530 811,1530 2000,1550 2050,1550 2100,1550 2150,1550 2200,1550 2250,1550 2300,1550 2350,1550 2400,1550 2450,1550 2500,1550 400,1585 811,1585 2500,1600 400,1625 811,1625 2010,1635 2500,1650 313,1666 913,1666 1913,1666 2113,1666 2010,1675 400,1680 810,1680 2500,1700 400,1720 810,1720 1325,1745 1355,1745 1325,1775 1355,1775 413,1866 813,1866 2013,1866 730,1895 2500,1900 730,1945 2500,1950
  other v2: 1835,460 950,1064.45 919.49,1094.96 980.51,1094.96 950,1125.47 1538.35,1272.23 1598.25,1272.23 1661.52,1272.23 1721.42,1272.23 1538.35,1332.13 1598.25,1332.13 1661.52,1332.13 1721.42,1332.13 1538.35,1395.4 1598.25,1395.4 1661.52,1395.4 1721.42,1395.4 1538.35,1455.3 1598.25,1455.3 1661.52,1455.3 1721.42,1455.3
I2C_SCL: R17.1 TP8.1 U4.4 U7.6 U10.A1 | length 2535.4
  Layer 1 - Top Layer w8: U7.6@1763.74,1353.92 1802.64,1353.92 1923.72,1475 v1(1955,1475) ; U4.4@1860.59,497.4 1860.59,515.59 1870,525 v1(1930,525) 2380,525 2405,550 TP8.1@2405,620 2348.62,676.38 R17.1@2348.62,740 v1(2348.62,788.62) ; U10.A1@1945,149.68 v1(1945,245)
  Layer 3 - PWR w8: v1(1930,525) 1930,380 1945,365 v1(1945,245) ; v1(1955,1475) 1845,1365 1845,1130 1885,1090 1885,1025 2070,840 2297.24,840 v1(2348.62,788.62)
I2C_SDA: R16.1 TP7.1 U4.6 U7.7 U10.A2 | length 2234.5
  Layer 1 - Top Layer w8: U7.7@1763.74,1373.61 1799.88,1373.61 1931.27,1505 v1(1945,1505) ; U4.6@1809.41,497.4 1809.41,599.41 1830,620 TP7.1@1965,620 2085,620 2150,685 v1(2150,795) ; U10.A2@1984.37,149.68 v1(1984.37,245)
  Layer 3 - PWR w8: v1(1945,1505) 1825,1385 1825,1120 1865,1080 1865,1015 2085,795 v1(2150,795) ; TP7.1@1965,620 1965,390 1984.37,370.63 v1(1984.37,245)
INTERRUPT: R15.1 TP6.1 U4.5 U7.8 | length 1875.7
  Layer 1 - Top Layer w8: U7.8@1763.74,1393.29 1796.58,1393.29 1875,1471.71 v1(1875,1490) ; U4.5@1835,497.4 1835,530 1855,550 2175,550 2185,560 TP6.1@2185,620 2185,695 2201.38,711.38 R15.1@2201.38,740 2201.38,776.38 2215,790 v1(2250,790)
  Layer 3 - PWR w8: v1(1875,1490) 1875,1465 1805,1395 1805,1110 1845,1070 1845,1005 2080,770 2230,770 v1(2250,790)
JTAG_TCK: J7.4 U7.25 U9.1 | length 814.4
  Layer 1 - Top Layer w8: U7.25@1496.02,1472.03 1472.97,1472.03 1465,1480 1465,1740 1524.69,1799.68 U9.1@1890,1799.68 J7.4@1890,1870
JTAG_TMS: J7.2 U7.24 U8.1 | length 1007.1
  Layer 1 - Top Layer w8: U7.24@1521.61,1497.62 1521.61,1518.39 1485,1555 1485,1730 1535,1780 1830,1780 1845,1765 1845,1715 1855,1705 1965,1705 1975,1715 1975,1790 1965.31,1799.68 U8.1@1940,1799.68 J7.2@1940,1870
LBOOST: L1.2 U3.20
NDRDY_HDC: R14.1 TP9.1 U7.9 U10.D2 | length 2287
  Layer 1 - Top Layer w8: U7.9@1763.74,1412.98 1794.35,1412.98 1845,1463.63 v1(1845,1490) ; U10.D2@1984.37,90.63 v1(2105,90.63) ; v1(2001.38,810) 2001.38,740.32 R14.1@2001.69,740
  Layer 3 - PWR w8: v1(1845,1490) 1845,1465 1785,1405 1785,1100 1825,1060 1825,986.38 v1(2001.38,810) 2061.38,750 2305,750 2330,725 2330,570 2285,525 2145,525 2115,495 TP9.1@2115,271 2115,100 v1@2105.63,90.63
NEN_BQ: R4.1 U3.5 | length 94.9
  Layer 1 - Top Layer w8: U3.5@989.37,1030 989.37,1010.63 999.69,1000.31 1014.69,1000.31 1025,990 R4.1@1025,958.62
NetBT1_1: BT1.1 D2.2
NetC33_2: C33.2 L4.1 L5.1 U7.1 | length 132.6
  Layer 1 - Top Layer w8: U7.1@1763.74,1255.5 1786.5,1255.5 1794,1248 1803.59,1248 1805,1249.41
  Layer 1 - Top Layer w15: 1805,1248.27 L5.1@1818,1248.27 1851.42,1248.27 C33.2@1855,1244.69 1855.31,1245 L4.1@1891,1245
NetC34_1: C34.1 E1. E1.1 L9.2 | length 130.7
  Layer 1 - Top Layer w15: C34.1@2414.65,1278.9 L9.2@2450,1278.9 ; L9.2@2450,1278.74 E1.1@2545.35,1278.74
  other v3: 2781.57,570.08 2978.43,570.08 2781.57,648.82 2978.43,648.82 2781.57,727.56 2978.43,727.56 2781.57,806.3 2978.43,806.3 2781.57,885.04 2978.43,885.04 2781.57,963.78 2978.43,963.78 2781.57,1042.52 2978.43,1042.52 2781.57,1121.26 2978.43,1121.26 2781.57,1200 2978.43,1200 2978.43,1278.74
NetC34_2: C34.2 R18.2 | length 40.6
  Layer 1 - Top Layer w15: R18.2@2334.69,1280 C34.2@2375.31,1280
NetC36_1: C36.1 C37.1 L4.2 L6.1 | length 102.4
  Layer 1 - Top Layer w15: L4.2@1926.73,1235 L4.2@1926.73,1245 C36.1@1926.73,1277.05 ; C36.1@1929.69,1280 L6.1@1990,1280
NetC36_2: C36.2 L5.2 L8.2 U7.2 | length 129.6
  Layer 1 - Top Layer w8: U7.2@1763.74,1275.18 1788.18,1275.18 1794.27,1281.27 1805,1281.27
  Layer 1 - Top Layer w15: 1805,1281.27 L8.2@1854,1281.27 1889.05,1281.27 C36.2@1890.31,1280
NetC38_1: C38.1 L6.2 L7.1 | length 52
  Layer 1 - Top Layer w15: L6.2@2030,1280 L7.1@2082,1280
NetC39_1: C39.1 C40.2 L7.2 | length 67.3
  Layer 1 - Top Layer w15: L7.2@2118,1280 C40.2@2185.31,1280
NetC40_1: C40.1 R18.1 R19.1 | length 70.6
  Layer 1 - Top Layer w15: C40.1@2224.69,1280 R18.1@2295.31,1280
NetC41_2: C41.2 U7.23 | length 83.4
  Layer 1 - Top Layer w8: C41.2@1530,1576.38 1530,1540 1541.3,1528.7 U7.23@1541.3,1497.62
NetD1_2: D1.2 J1.2
NetJ4_1: J4.1 Q2.C2 | length 259.8
  Layer 1 - Top Layer w8: 1075.32,1639.68 Q2.C2@1075.32,1675.16
  Layer 1 - Top Layer w30: J4.1@930,1540 930,1590 950,1610 1060,1610 1075.32,1625.32 1075.32,1639.68
NetJ5_2: J5.2 U7.40 | length 1795.2
  Layer 1 - Top Layer w8: v1(1215,1090) 1440,1090 1455,1105 1455,1175 1480,1200 1570,1200 1580.67,1210.67 U7.40@1580.67,1229.91
  Layer 4 - Bottom Layer w8: J5.2@90,1230 155,1230 200,1185 200,1115 295,1020 382.55,1020 388.42,1014.13 755.73,1014.13 794.85,975 1035,975 1150,1090 v1(1215,1090)
NetJ5_3: J5.3 U7.41 | length 1746.2
  Layer 1 - Top Layer w8: v1(1215,1060) 1440,1060 1475,1095 1475,1155 1500,1180 1575,1180 1600.35,1205.35 U7.41@1600.35,1229.91
  Layer 4 - Bottom Layer w8: J5.3@90,1130 155,1130 290,995 746.57,995 786.57,955 1043.28,955 1148.28,1060 v1(1215,1060)
NetJ5_4: J5.4 U7.42 | length 1738.3
  Layer 1 - Top Layer w8: v1(1215,1030) 1440,1030 1495,1085 1495,1135 1520,1160 1580,1160 1620.04,1200.04 U7.42@1620.04,1229.91
  Layer 4 - Bottom Layer w8: J5.4@90,1030 225,1030 280,975 738.28,975 778.28,935 1051.57,935 1146.57,1030 v1(1215,1030)
NetJ5_5: J5.5 U7.43 | length 1754.1
  Layer 1 - Top Layer w8: v1(1215,1000) 1440,1000 1515,1075 1515,1120 1535,1140 1585,1140 1639.72,1194.72 U7.43@1639.72,1229.91
  Layer 4 - Bottom Layer w8: J5.5@90,930 195,930 220,955 730,955 770,915 1059.85,915 1144.85,1000 v1(1215,1000)
NetJ6_1: J6.1 R19.2 | length 180.3
  Layer 1 - Top Layer w15: J6.1@2260,1060 R19.2@2260,1240.31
